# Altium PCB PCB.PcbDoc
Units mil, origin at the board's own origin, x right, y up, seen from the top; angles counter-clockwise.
Board outline 2745.03 x 2005.03 mil, 2 copper layers (Top Layer, Bottom Layer); 57 components, 30 nets, 243 pads, 20 vias.
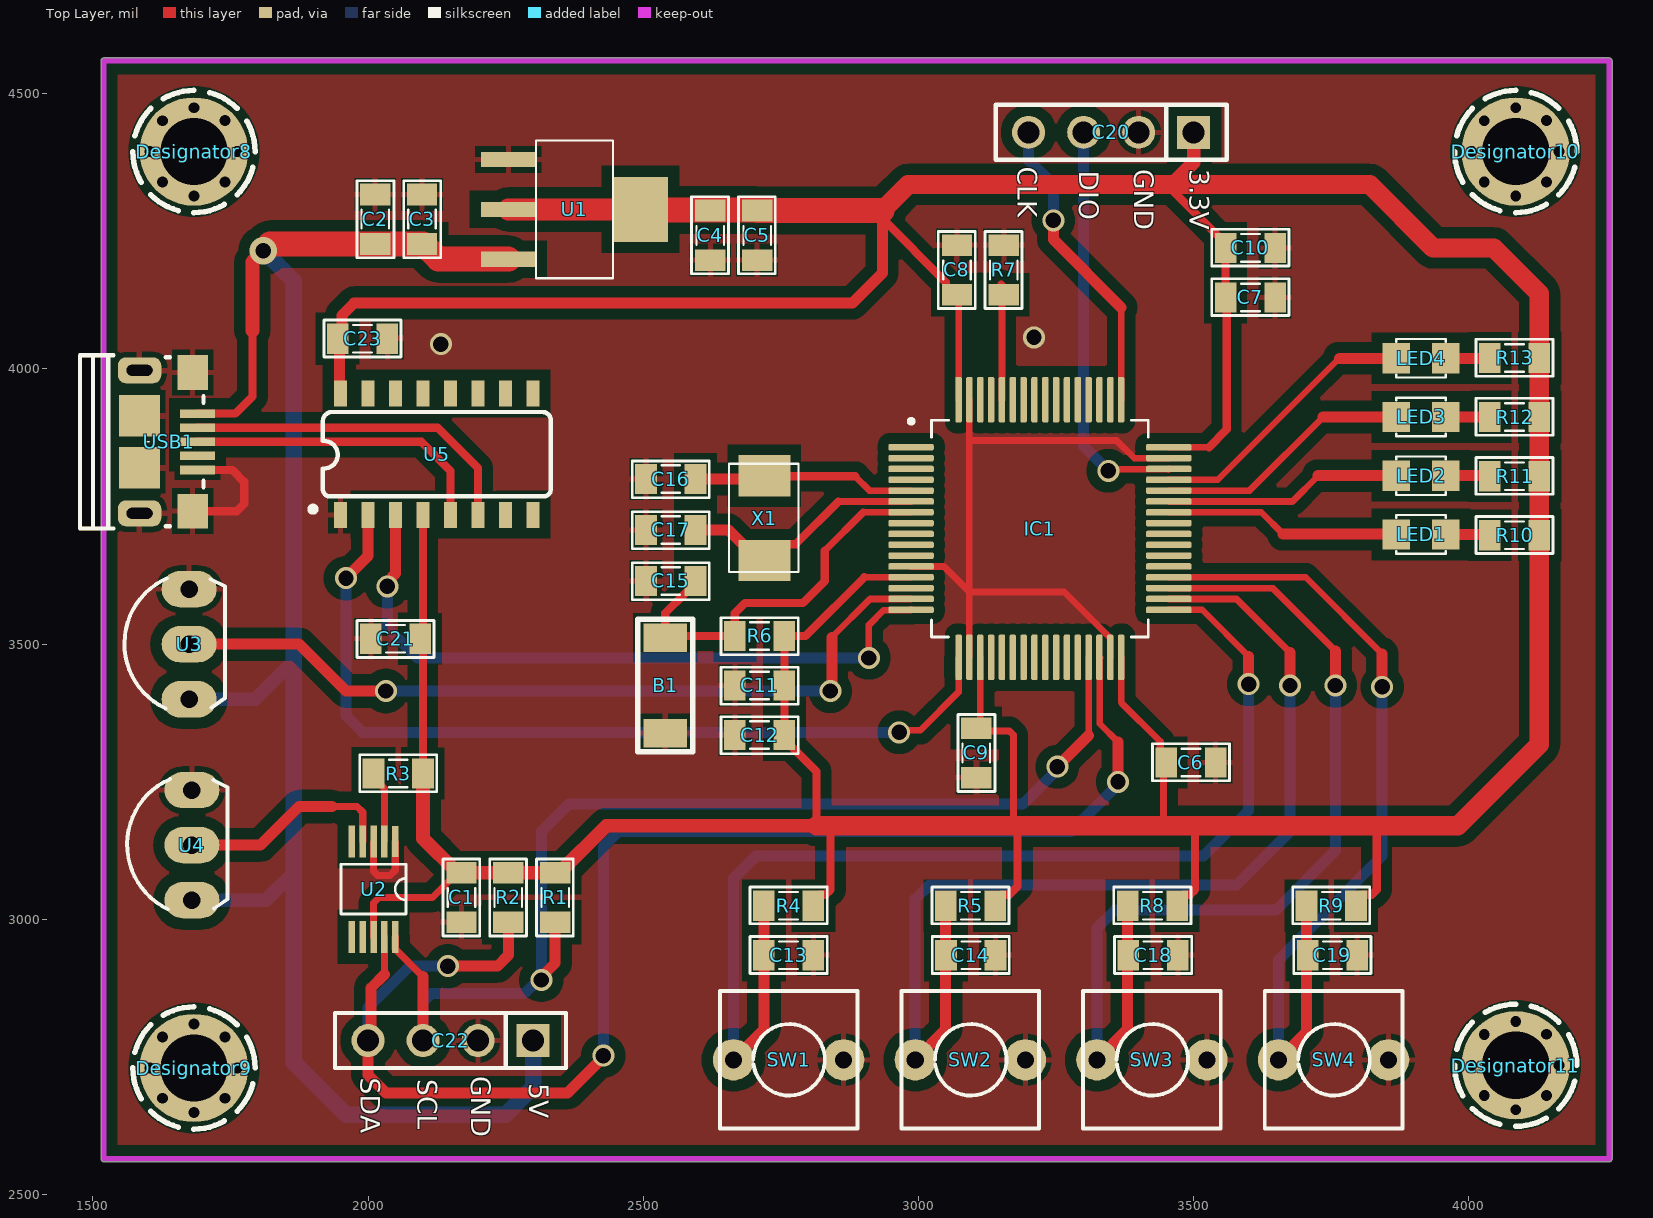
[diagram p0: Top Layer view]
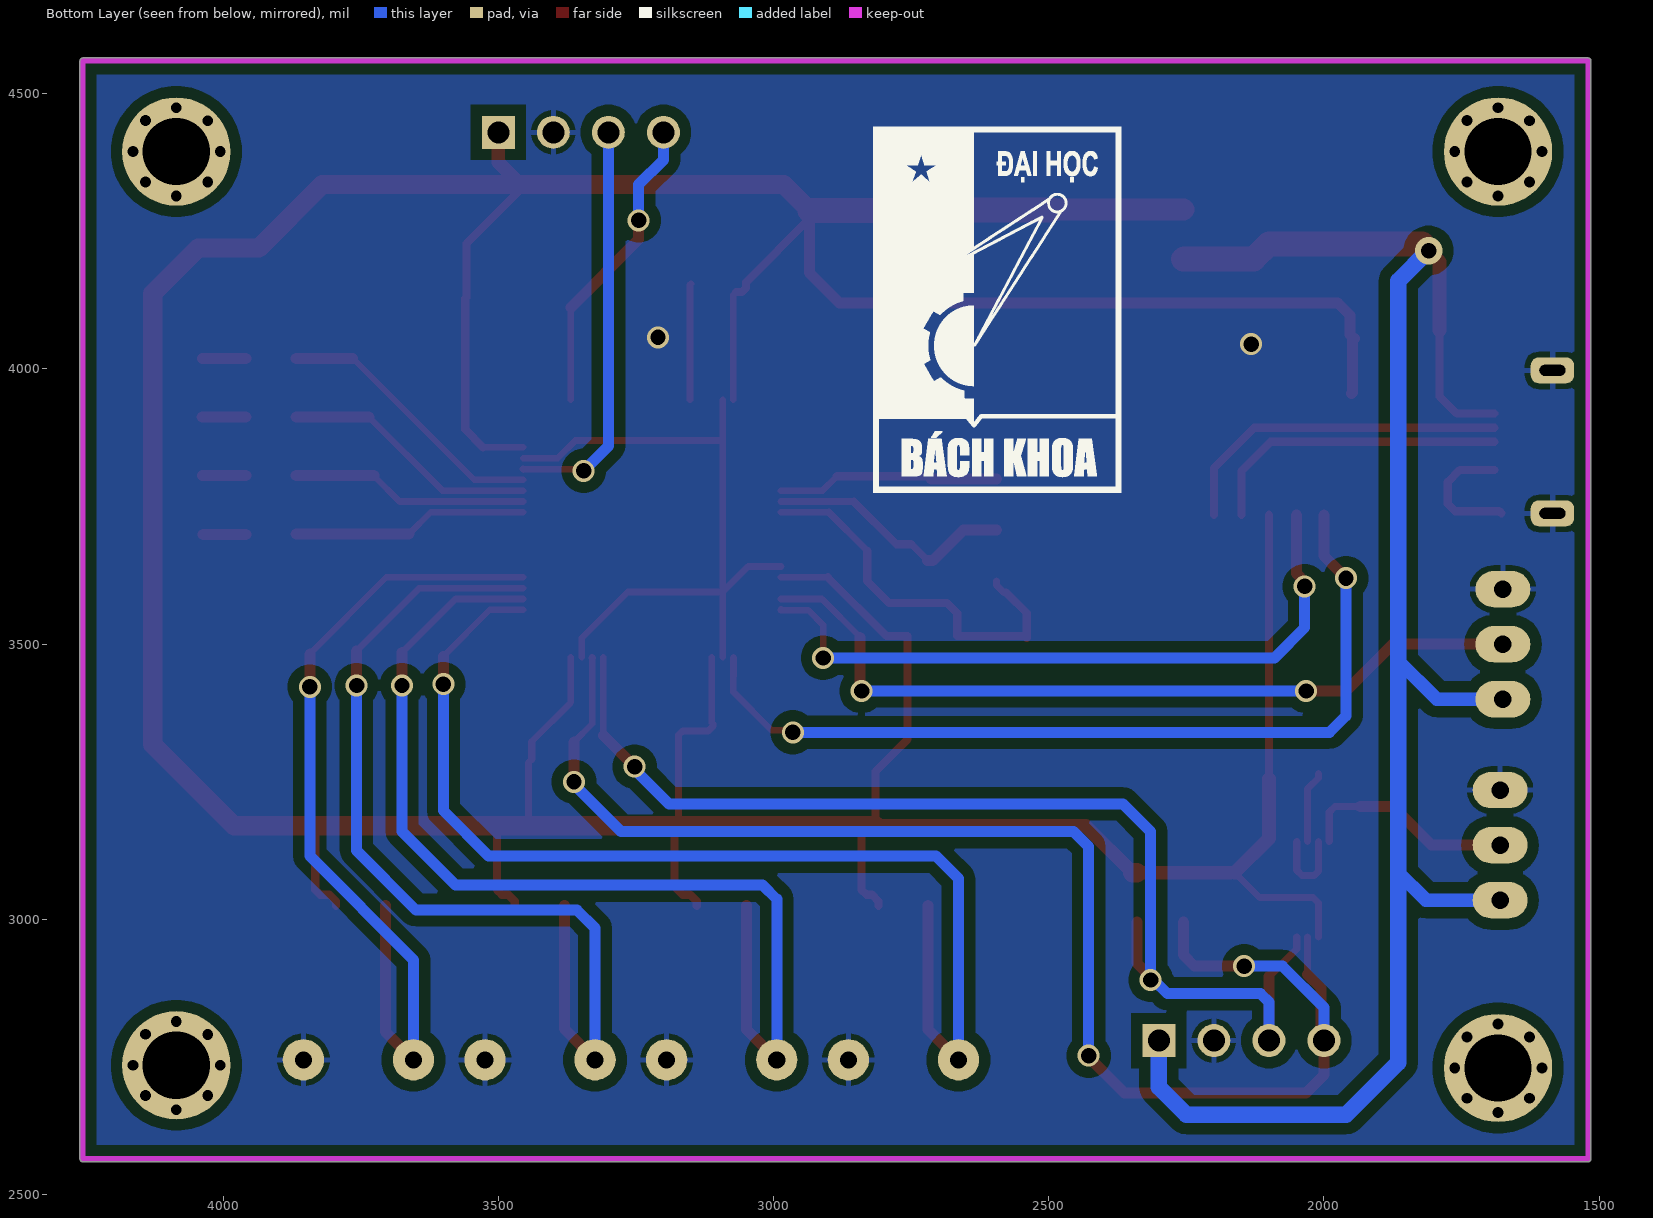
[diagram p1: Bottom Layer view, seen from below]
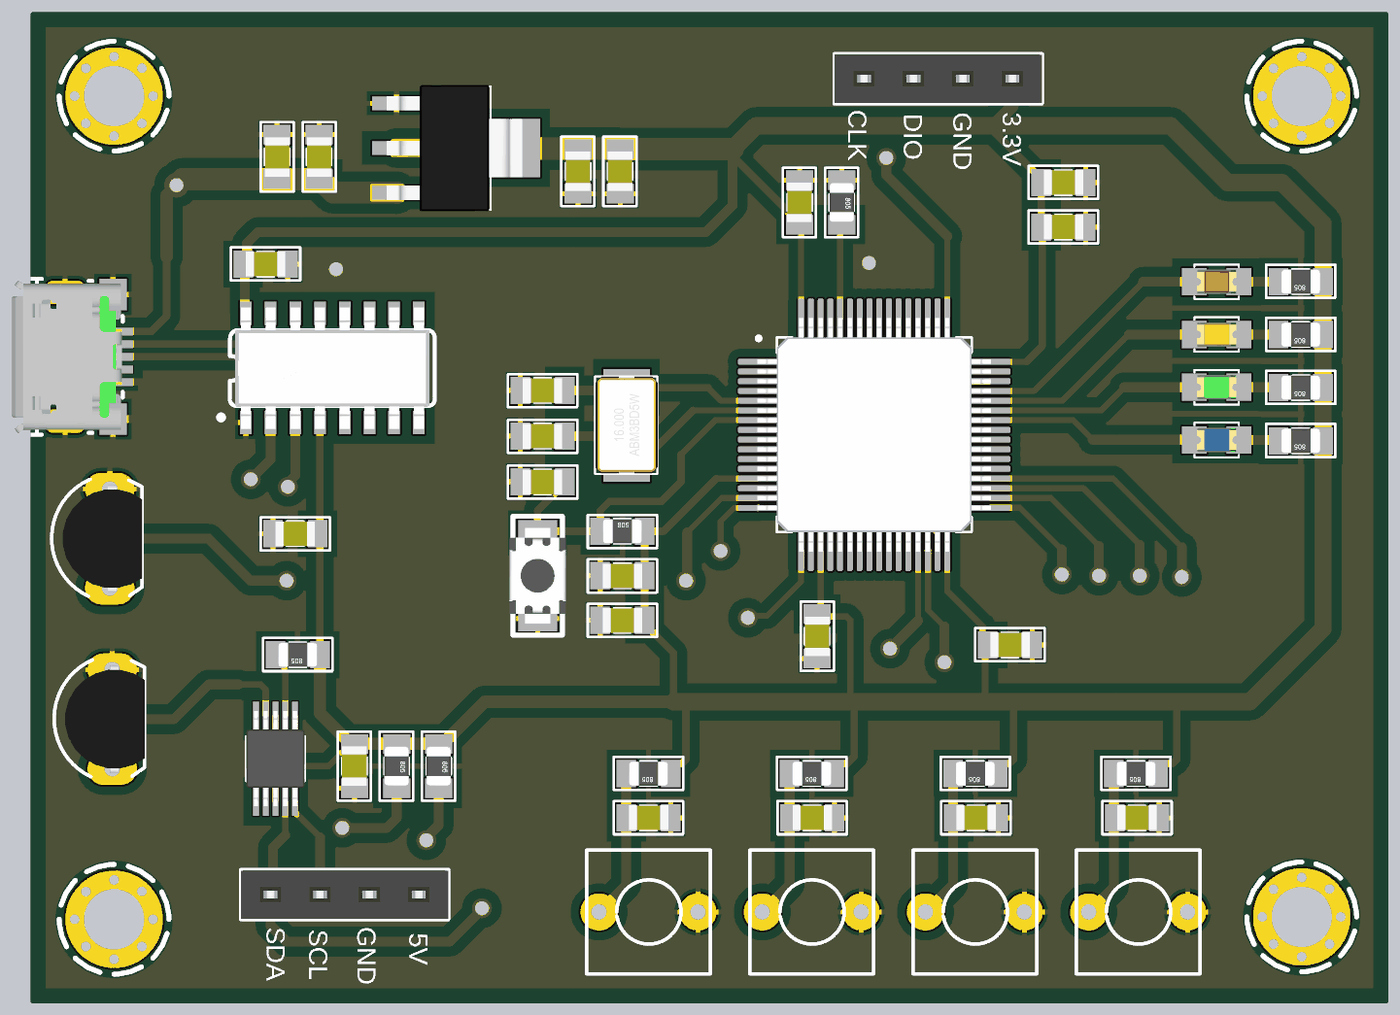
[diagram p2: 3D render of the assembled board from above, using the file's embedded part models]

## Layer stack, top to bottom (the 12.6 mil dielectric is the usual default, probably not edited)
Top Solder: solder mask 0.4, Solder Resist, Dk 3.5
Top Layer: signal copper 1.4
Dielectric 1: dielectric 12.6, FR-4, Dk 4.8
Bottom Layer: signal copper 1.4
Bottom Solder: solder mask 0.4, Solder Resist, Dk 3.5

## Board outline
1520,2559.99 cw(c1520,2565) 1514.98,2565 1514.98,4560 cw(c1520,4560) 1520,4565.02 4255,4565.02 cw(c4255,4560) 4260.02,4560 4260.02,2565 cw(c4255,2565) 4255,2559.99

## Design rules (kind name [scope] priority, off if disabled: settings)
Clearance Clearance_1 [InNet('GND')] p1: gap=20 ignorepadtopadclearanceinfootprint=TRUE
Clearance [All] p2: gap=15 ignorepadtopadclearanceinfootprint=TRUE
PolygonConnect [All] p1: thpad.connectstyle=Relief thpad.reliefconductorwidth=10 thpad.reliefentries=4 thpad.polygonreliefangle="90 Angle" thpad.airgapwidth=10 smdpad.connectstyle=Relief smdpad.reliefconductorwidth=10 smdpad.reliefentries=4 smdpad.polygonreliefangle="90 Angle" smdpad.airgapwidth=10 via.connectstyle=Direct via.reliefconductorwidth=10 via.reliefentries=4 via.polygonreliefangle="90 Angle" via.airgapwidth=10
RoutingVias [All] p1: holewidth=28 width=50 viastyle="Through Hole" minholewidth=28 minwidth=40 maxholewidth=28 maxwidth=50
SolderMaskExpansion [All] p1: expansion=4 istentingtop=FALSE
Width [All] p1: maxlimit=100 minlimit=10 preferedwidth=10
30 further rules are at their usual default settings.

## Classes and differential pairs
component class SCHE: B1 C1 C2 C3 C4 C5 C6 C7 C8 C9 C10 C11 C12 C13 C14 C15 C16 C17 C18 C19 C20 C21 C22 C23 IC1 LED1 LED2 LED3 LED4 R1 R2 R3 R4 R5 R6 R7 R8 R9 R10 R11 R12 R13 SW1 SW2 SW3 SW4 U1 U2 U3 U4 U5 USB1 X1

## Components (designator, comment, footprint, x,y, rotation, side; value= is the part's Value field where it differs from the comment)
B1 "Button 3x4x2.5" "Button 3x4x2.5" 2540,3425 r270 top
C1 "100nF" CAP_0805 2258.11,3042.15 r270 top value=33p
C2 "100nF" CAP_0805 1925,4270 r90 top value=33p
C3 "10uF" CAP_0805 2010,4270 r90 top value=33p
C4 "10uF" CAP_0805 2710,4245 r270 top value=33p
C5 "100nF" CAP_0805 2795,4245 r270 top value=33p
C6 "100nF" CAP_0805 3497.15,3196.89 r180 top value=33p
C7 "100nF" CAP_0805 3605.15,4041.89 r180 top value=33p
C8 "100nF" CAP_0805 3158.11,4182.15 r270 top value=33p
C9 "100nF" CAP_0805 3016.89,3300.35 r90 top value=33p
C10 "4.7uF" CAP_0805 3605.15,4131.89 r180 top value=33p
C11 "100nF" CAP_0805 2709.32,3513.11 r0 top value=33p
C12 "1uF" CAP_0805 2709.32,3423.11 r0 top value=33p
C13 "100nF" CAP_0805 2766.32,2846.89 r180 top value=33p
C14 "100nF" CAP_0805 3097.27,2846.89 r180 top value=33p
C15 "100nF" CAP_0805 2547.85,3703.11 r0 top value=33p
C16 "22pF" CAP_0805 2547.85,3888.11 r0 top value=33p
C17 "22pF" CAP_0805 2547.85,3795.61 r0 top value=33p
C18 "100nF" CAP_0805 3428.5,2846.89 r180 top value=33p
C19 "100nF" CAP_0805 3754.17,2846.89 r180 top value=33p
C20 "JP4" JP4-C1T 3500,4430 r180 top
C21 "100nF" CAP_0805 2047.85,3598.11 r0 top value=33p
C22 "JP4" JP4-C1T 2300,2780 r180 top
C23 "100nF" CAP_0805 1992.15,3966.89 r180 top value=33p
Designator8 "Comment" HOLD 1683.73,4395 r0 top
Designator9 "Comment" HOLD 1683.73,2730.12 r0 top
Designator10 "Comment" HOLD 4085,4395 r0 top
Designator11 "Comment" HOLD 4085,2735 r0 top
IC1 "STM32F103RCT6" STM32F103RCT6 3225,3720 r0 top
LED1 "LED" LED-0805-Blue 3958,3699.5 r180 top value="LED 3 ly Single Colour"
LED2 "LED" LED-0805-Green 3958,3806.17 r180 top value="LED 3 ly Single Colour"
LED3 "LED" LED-0805-Orange 3958,3912.83 r180 top value="LED 3 ly Single Colour"
LED4 "LED" LED-0805-Red 3958,4019.5 r180 top value="LED 3 ly Single Colour"
R1 "10k" RES-SMD-0805 2340,3040 r270 top
R2 "10k" RES-SMD-0805 2255,3040 r270 top
R3 "1k" RES-SMD-0805 2055,3265 r180 top
R4 "10k" RES-SMD-0805 2764.17,3025 r180 top
R5 "10k" RES-SMD-0805 3094.45,3025 r180 top
R6 "10k" RES-SMD-0805 2711.47,3515 r0 top
R7 "100k" RES-SMD-0805 3155,4180 r270 top
R8 "10k" RES-SMD-0805 3425,3025 r180 top
R9 "10k" RES-SMD-0805 3750,3025 r180 top
R10 "1k" RES-SMD-0805 4083,3698 r180 top
R11 "1k" RES-SMD-0805 4083,3805.33 r180 top
R12 "1k" RES-SMD-0805 4083,3912.67 r180 top
R13 "1k" RES-SMD-0805 4083,4020 r180 top
SW1 "SW" SW2 2864.17,2745 r180 top value="SW chip 2 pin"
SW2 "SW" SW2 3194.17,2745 r180 top value="SW chip 2 pin"
SW3 "SW" SW2 3524.17,2745 r180 top value="SW chip 2 pin"
SW4 "SW" SW2 3854.17,2745 r180 top value="SW chip 2 pin"
U1 "LM1117-ADJ" LM1117-SOP 2305,4290 r270 top
U2 "ADS1115IDGSR" VSOP-10_19.6_230_57X12_SMD 2010,3055 r270 top
U3 "LM35" QTO-92 1675,3500 r90 top
U4 "LM35" QTO-92 1680,3135 r90 top
U5 "CH340C" SO016 2125,3845.24 r0 top
USB1 "USB Micro 5p DIP" "USB Micro 5p DIP" 1585,3867.76 r270 top
X1 "8Mhz" "XTAL 5032 SMD" 2720,3730 r90 top value=4Mhz

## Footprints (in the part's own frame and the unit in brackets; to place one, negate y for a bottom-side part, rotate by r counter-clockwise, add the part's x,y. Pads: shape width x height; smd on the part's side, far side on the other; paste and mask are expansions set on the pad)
"Button 3x4x2.5" [mm]
  rect 1.3x2 smd: 1(-2.2,0) 2(2.2,0)
  silkscreen extent -3.05,-1.27 3.05,1.27, body extent -2.45,-1.45 2.45,1.45, height 2
CAP_0805 [mil]
  rect 39.37x55 smd: 1(-42.85,-88.11) 2(47.15,-88.11)
  silkscreen extent -68,-122 72,-55, body extent -38,-114 42,-64, height 24
HOLD [mm]
  round 0.5 hole 0.5: 2(-2.025,0) 2(-1.45,-1.4) 2(-1.45,1.425) 2(0,-2.05) 2(0,2.025) 2(1.429,-1.4) 2(1.429,1.434) 2(2,0)
  round 5 hole 3.1: 10(0,0)
  silkscreen extent -2.82,-2.82 2.82,2.82
JP4-C1T [mm] "4 row, straight, gold plating"
  rect 1.52x1.52 hole 1.02: 1(0,0)
  round 1.52 hole 1.02: 2(2.54,0) 3(5.08,0) 4(7.62,0)
  silkscreen extent -1.52,-1.27 9.14,1.27, body extent -1.52,-1.25 9.14,1.25, height 8.51
LED-0805-Blue [mil]
  rect 50x55 smd: 1(0,0) 2(90,0)
  silkscreen extent 0,-35 90,35, body extent 5,-25 85,25, height 43
LED-0805-Green [mil]
  rect 50x55 smd: 1(0,0) 2(90,0)
  silkscreen extent 0,-35 90,35, body extent 5,-25 85,25, height 43
LED-0805-Orange [mil]
  rect 50x55 smd: 1(0,0) 2(90,0)
  silkscreen extent 0,-35 90,35, body extent 5,-25 85,25, height 43
LED-0805-Red [mil]
  rect 50x55 smd: 1(0,0) 2(90,0)
  silkscreen extent 0,-35 90,35, body extent 5,-25 85,25, height 43
LM1117-SOP [mm]
  rect 0.7x2.54 smd: 1(-2.3,-1.27) 2(0,-1.27) 3(2.3,-1.27)
  rect 3x2.54 smd: 2(0,4.826)
  silkscreen extent -3.18,0 3.18,3.56, body extent -3.25,-1.78 3.25,5.18, height 1.68
QTO-92 [mil] "TO-92"
  oval 66x100 hole 32: 1(-100,0) 2(0,0) 3(100,0)
  silkscreen extent -117,-65 120,118, body extent -109,-66 109,95, height 245
RES-SMD-0805 [mil]
  rect 39.37x55 smd: 1(-45,0) 2(45,0)
  silkscreen extent -70,-34 70,33, body extent -39,-25 39,25, height 31
SO016 [mm]
  rect 0.6x1.2 smd: 1(-4.445,-2.8) 2(-3.175,-2.8) 3(-1.905,-2.8) 4(-0.635,-2.8) 5(0.635,-2.8) 6(1.905,-2.8) 7(3.175,-2.8) 8(4.445,-2.8) 9(4.445,2.8) 10(3.175,2.8) 11(1.905,2.8) 12(0.635,2.8) 13(-0.635,2.8) 14(-1.905,2.8) 15(-3.175,2.8) 16(-4.445,2.8)
  silkscreen extent -5.84,-2.67 5.26,1.95, body extent -4.99,-3.13 4.99,3.1, height 1.58
STM32F103RCT6 [mm]
  rrect50% 2.1x0.3 smd: 1(-6.057,3.499) 2(-6.057,2.999) 3(-6.057,2.499) 4(-6.057,1.999) 5(-6.057,1.499) 6(-6.057,0.999) 7(-6.057,0.499) 8(-6.057,-0.001) 9(-6.057,-0.501) 10(-6.057,-1.001) 11(-6.057,-1.501) 12(-6.057,-2.001) 13(-6.057,-2.501) 14(-6.057,-3.001) 15(-6.057,-3.501) 16(-6.057,-4.001) 33(5.833,-4.001) 34(5.833,-3.501) 35(5.833,-3.001) 36(5.833,-2.501) 37(5.833,-2.001) 38(5.833,-1.501) 39(5.833,-1.001) 40(5.833,-0.501) 41(5.833,-0.001) 42(5.833,0.499) 43(5.833,0.999) 44(5.833,1.499) 45(5.833,1.999) 46(5.833,2.499) 47(5.833,2.999) 48(5.833,3.499)
  rrect50% 0.3x2.1 smd: 17(-3.862,-6.196) 18(-3.362,-6.196) 19(-2.862,-6.196) 20(-2.362,-6.196) 21(-1.862,-6.196) 22(-1.362,-6.196) 23(-0.862,-6.196) 24(-0.362,-6.196) 25(0.138,-6.196) 26(0.638,-6.196) 27(1.138,-6.196) 28(1.638,-6.196) 29(2.138,-6.196) 30(2.638,-6.196) 31(3.138,-6.196) 32(3.638,-6.196) 49(3.638,5.694) 50(3.138,5.694) 51(2.638,5.694) 52(2.138,5.694) 53(1.638,5.694) 54(1.138,5.694) 55(0.638,5.694) 56(0.138,5.694) 57(-0.362,5.694) 58(-0.862,5.694) 59(-1.362,5.694) 60(-1.862,5.694) 61(-2.362,5.694) 62(-2.862,5.694) 63(-3.362,5.694) 64(-3.862,5.694)
  silkscreen extent -6.15,-5.25 4.89,4.8, body extent -6.11,-6.25 5.89,5.75, height 1.74
SW2 [mil] "SW button 2pin, 250x 250 mil"
  round 75 hole 31: 1(0,0) 2(200,0)
  silkscreen extent -25,-125 225,125
"USB Micro 5p DIP" [mm]
  rect 0.4x1.6 smd mask+0.05: 1(-1.3,2.675) 2(-0.65,2.675) 3(0,2.675) 4(0.65,2.675) 5(1.3,2.675)
  rrect60% 1.2x2 hole 0.5 slot 1.2 at 90 deg: 5(-3.3,0) 5(3.3,0)
  rect 1.6x1.4 smd: 5(-3.2,2.45) 5(3.2,2.45)
  rect 1.9x1.9 smd paste-10: 5(-1.2,0) 5(1.2,0)
  silkscreen extent -4,-2.75 4,2.95, body extent -3.93,-2.76 3.93,2.9, height 2.85
VSOP-10_19.6_230_57X12_SMD [mm] "VSOP Package"
  rect 1.45x0.3 smd mask+0.076: 1(-2.2,1)
  rect 1.47x0.3 smd mask+0.076: 2(-2.2,0.5) 3(-2.2,0) 4(-2.2,-0.5) 5(-2.2,-1) 6(2.2,-1) 7(2.2,-0.5) 8(2.2,0) 9(2.2,0.5) 10(2.2,1)
  silkscreen extent -1.15,-1.5 1.15,1.5, body extent -2.45,-1.5 2.45,1.5, height 1.07
"XTAL 5032 SMD" [mm] "SMD 5032 XTAL Footprint"
  rect 1.9x2.4 smd: 1(-1.981,0) 2(1.93,0)
  silkscreen extent -2.51,-1.57 2.49,1.63, body extent -2.5,-1.6 2.5,1.6, height 1.31

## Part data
C1 C2 C3 C4 C5 C6 C7 C8 C9 C10 C11 C12 C13 C14 C15 C16 C17 C18 C19 C21 C23: library part CapSMD, "Capacitor"
C20 C22: "WR-PHD 2.54 mm Angled Socket Header", Manufacturer="W¨¹rth Elektronik eiSos GmbH", partNo=613004143121
LED1 LED2 LED3 LED4: "LED Single colour Green and Red"
R1 R2 R3 R7: library part "Resistor - SMD", "Resistor", Manufacturer="Generic Components"
R4 R5 R6 R8 R9 R10 R11 R12 R13: library part "Resistor - SMD", "Resistor SMD", Manufacturer="Generic Components"
SW1 SW2 SW3 SW4: library part SW2, "Switch button 2 pin"
U1: "800mA Low-Dropout Linear Regulator"
U2: library part IC_ADS1115IDGSR, "Analog to Digital Converters - ADC 16B ADC w/ Int MUX PGA Comp Osc & Ref", Alternate Part Number-1=NA, Case/Package=MSOP-10, Manufacturer="Texas Instruments", Supplier Part Number-1=595-ADS1115IDGSR
U3 U4: "Teminal"
U5: "USB to serial chip CH340", Package=Package
USB1: "USB Type B"
X1: library part XT2, "Crystal For all Crystal 2pin."

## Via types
v1: diameter 40, hole 28, Top Layer to Bottom Layer, tented both sides, 19 vias
v2: diameter 50, hole 28, Top Layer to Bottom Layer, tented both sides, 1 vias

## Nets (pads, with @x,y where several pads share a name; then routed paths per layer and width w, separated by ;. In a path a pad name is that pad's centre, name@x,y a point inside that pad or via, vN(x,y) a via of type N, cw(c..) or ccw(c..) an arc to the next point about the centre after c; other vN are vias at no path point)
+3.3V: C1.1 C4.1 C5.1 C6.2 C7.2 C8.2 C9.2 C10.2 C11.2 C12.2 C20.1 C21.2 C23.2 IC1.13 IC1.19 IC1.32 IC1.48 IC1.64 R1.1 R2.1 R3.1 R4.1 R5.1 R6.2 R8.1 R9.1 R10.1 R11.1 R12.1 R13.1 U1.2 U2.8 U5.4 U5.16 | length 10158.1
  Top Layer w12: 2901.54,3621.54 IC1.13 ; IC1.64 C8.2@3072.95,4135 ; C9.2@3110,3355 3112.32,3357.32 IC1.19 ; IC1.32 3368.23,3394.27 3439.37,3323.13 ; IC1.48 3527.76,3857.76
  Top Layer w13: U2.8 2010,3030 2020,3040 2117.19,3040 2149,3071.81 2158.28,3081.09 C1.1@2166.09,3081.09 ; C1.1@2162.19,3085 C1.1 ; C9.2@3110,3355 3110,3351 3118.5,3342.5 3164.88,3342.5 3172.5,3334.88 3172.5,3170 ; 3439.37,3323.13 3439.37,3290.63 3445,3285 3445,3170
  Top Layer w15: R3.1@2100,3255 2100,3510 U5.4 ; R4.1 2809.17,3032.81 2821.36,3045 2831.21,3045 2840,3053.79 2840,3170 ; 2815,3170 2815,3268.65 2756.47,3327.19 C12.2 C11.2 R6.2 2795,3515 2901.54,3621.54 ; 2934.33,4273.17 3050,4157.5 3050,4147.19 3057.49,4139.7 C8.2@3067.8,4139.7 ; R5.1 3139.45,3032.81 3151.63,3045 3165,3045 3180,3060 3180,3170 ; 3460,4335 3460,4325.81 3558,4227.81 C10.2 C7.2 3560,4128 3560,3890 3527.76,3857.76 ; R8.1 3470,3032.82 3482.18,3045 3493.71,3045 3502.5,3053.79 3502.5,3170 ; R9.1 3795,3032.81 3807.19,3045 3823.71,3045 3832.5,3053.79 3832.5,3170
  Top Layer w20: U5.16 1948.19,3957.28 1948.19,4051.81 C23.2 1952.31,4062.31 1952.31,4097.31 1975,4120 2085,4120 2880,4120 2934.33,4174.33 2934.33,4273.17 2934.33,4287.85
  Top Layer w25: R3.1@2100,3255 2100,3147.18 C1.1@2162.19,3085 ; C1.1 R1.1 ; R1.1@2347.81,3085 2432.82,3170 2815,3170 ; 3460,4335 3500,4375 C20.1
  Top Layer w35: R1.1 R1.1@2347.81,3085 ; 2815,3170 2840,3170 3172.5,3170 3180,3170 3445,3170 3502.5,3170 3832.5,3170 3980,3170 4128,3318 R10.1 R11.1 R12.1 R13.1 4128,4137 4045,4220 3935,4220 3820,4335 3460,4335 2981.48,4335 2935.74,4289.26 2934.33,4287.85
  Top Layer w40: U1.2@2255,4290 U1.2@2495,4290
  Top Layer w45: U1.2@2495,4290 2496.07,4288.93 2621.89,4288.93 2705.82,4288.93 C5.1 2934.33,4287.85
+5: C2.1 C3.1 C22.1 U1.3 U3.1 U4.1 USB1.1 | length 3349.9
  Top Layer w15: USB1.1 1758.94,3918.94 1790,3950 1790,4070
  Top Layer w25: 1790,4070 1790,4195 v2(1810,4215)
  Top Layer w45: v2(1810,4215) 1822.15,4227.15 C2.1 C3.1 2100.3,4227.15 2127.44,4200 2254.45,4200 U1.3
  Bottom Layer w25: U3.1 1795,3400 1865,3470 ; U4.1 1815,3035 1865,3085
  Bottom Layer w30: v2(1810,4215) 1865,4160 1865,3470 1865,3085 1865,2740 1960,2645 2250,2645 2300,2695 C22.1
BUT0: C13.2 IC1.33 R4.2 SW1.2 | length 2079.7
  Top Layer w12: IC1.33 3515.48,3562.48 3600,3477.96
  Top Layer w20: SW1.2 2719.17,2800 R4.2 ; v1(3600,3427.5) 3600,3477.96
  Bottom Layer w20: SW1.2 2664.17,3074.17 2705,3115 3517.5,3115 3600,3197.5 v1(3600,3427.5)
BUT1: C14.2 IC1.34 R5.2 SW2.2 | length 1912.1
  Top Layer w12: IC1.34 3577.83,3582.17 3675,3485
  Top Layer w20: SW2.2 3049.45,2800.28 R5.2 ; v1(3675,3425) 3675,3485
  Bottom Layer w20: SW2.2 2994.17,3036.67 3020,3062.5 3577.5,3062.5 3675,3160 v1(3675,3425)
BUT2: C18.2 IC1.35 R8.2 SW3.2 | length 1746.7
  Top Layer w12: IC1.35 3643.15,3601.85 3757.5,3487.5
  Top Layer w20: SW3.2 3380,2800.83 R8.2 ; v1(3757.5,3425) 3757.5,3487.5
  Bottom Layer w20: SW3.2 3324.17,2984.17 3357.5,3017.5 3650,3017.5 3757.5,3125 v1(3757.5,3425)
BUT3: C19.2 IC1.36 R9.2 SW4.2 | length 1562
  Top Layer w12: IC1.36 3703.46,3621.54 3842.5,3482.5
  Top Layer w20: SW4.2 3705,2795.83 R9.2 ; v1(3842.5,3422.5) 3842.5,3482.5
  Bottom Layer w20: SW4.2 3654.17,2926.67 3842.5,3115 v1(3842.5,3422.5)
CH340_RXD: IC1.16 U5.3 | length 1256.9
  Top Layer w12: v1(2910,3475) 2910,3535 2936.89,3561.89 IC1.16@2985.94,3561.89
  Top Layer w13: IC1.16@2985.94,3561.89 IC1.16
  Top Layer w20: v1(2035,3605) 2035,3613.12 2050,3628.12 U5.3
  Bottom Layer w20: v1(2035,3605) 2035,3530 2090,3475 v1(2910,3475)
CH340_TXD: IC1.17 U5.2 | length 1600.3
  Top Layer w12: v1(2965,3340) 2968.62,3343.62 3003.62,3343.62 3072.95,3412.95 IC1.17@3072.95,3441.82
  Top Layer w13: IC1.17@3072.95,3441.82 IC1.17
  Top Layer w20: v1(1960,3620) 2000,3660 U5.2
  Bottom Layer w20: v1(1960,3620) 1960,3370 1990,3340 v1(2965,3340)
D_N: U5.6 USB1.2 | length 625.1
  Top Layer w15: USB1.2 2126.65,3893.35 2200,3820 U5.6
D_P: U5.5 USB1.3 | length 561.5
  Top Layer w15: USB1.3 2097.24,3867.76 2150,3815 U5.5
GND: B1.2 C1.2 C2.2 C3.2 C4.2 C5.2 C6.1 C7.1 C8.1 C9.1 C10.1 C11.1 C12.1 C13.1 C14.1 C15.1 C16.1 C17.1 C18.1 C19.1 C20.2 C21.1 C22.2 C23.1 IC1.12 IC1.18 IC1.31 IC1.47 IC1.63 R7.1 SW1.1 SW2.1 SW3.1 SW4.1 U1.1 U2.1 U2.3 U3.3 U4.3 U5.1 USB1.5 | length 1688.8
  Top Layer w12: v1@2130,4042.5 v1(2132.5,4045) ; IC1.12 3046.28,3641.22 3092.64,3594.86 ; IC1.18 3092.64,3594.86 ; IC1.63 3092.64,3870 ; IC1.31 3348.54,3511.31 3264.99,3594.86 3092.64,3594.86 ; IC1.47 3391.93,3838.07 3360,3870 3092.64,3870 ; 3092.64,3594.86 3092.64,3870
  Top Layer w13: U2.3 2010,3087.62 2017.62,3080 2040,3080 2049.37,3089.37 U2.1
  Top Layer w15: USB1.5@1677.52,3737.83 1681.46,3741.77 1761.77,3741.77 1775,3755 1775,3795 1753.43,3816.57 USB1.5@1690.32,3816.57
  other v1: 3210,4057.5
LED0: IC1.42 LED1.2 | length 430
  Top Layer w12: IC1.42 3622.85,3739.65 3662.5,3700
  Top Layer w13: LED1.2@3867.5,3700 LED1.2
  Top Layer w20: 3662.5,3700 LED1.2@3867.5,3700
LED1: IC1.43 LED2.2 | length 432.8
  Top Layer w12: IC1.43 3679.33,3759.33 3726.17,3806.17
  Top Layer w20: 3726.17,3806.17 LED2.2
LED2: IC1.44 LED3.2 | length 468.8
  Top Layer w12: IC1.44 3601.52,3779.02 3735.33,3912.83
  Top Layer w20: 3735.33,3912.83 LED3.2
LED3: IC1.45 LED4.2 | length 504.8
  Top Layer w12: IC1.45 3543.7,3798.7 3764.5,4019.5
  Top Layer w20: 3764.5,4019.5 LED4.2
LM35_ADC1: IC1.15 U3.2 | length 1471.6
  Top Layer w12: 2842.5,3512.5 2912.17,3582.17 IC1.15
  Top Layer w20: U3.2 1875,3500 1960,3415 v1(2032.5,3415) ; v1(2840,3415) 2842.5,3417.5 2842.5,3512.5
  Bottom Layer w20: v1(2032.5,3415) v1(2840,3415)
LM35_ADC2: U2.4 U4.2 | length 396.7
  Top Layer w13: 1935,3205 1980,3205 1990.32,3194.68 U2.4
  Top Layer w20: U4.2 1805,3135 1875,3205 1935,3205
NetB1_1: B1.1 C15.2 IC1.7 R6.1 | length 726.3
  Top Layer w12: 2899.65,3739.65 IC1.7
  Top Layer w13: B1.1 B1.1@2543.39,3515 ; C15.2@2577.3,3594 2581.81,3594 2595,3607.19 C15.2 ; 2830,3670 2899.65,3739.65
  Top Layer w15: B1.1 2540,3556.7 C15.2@2577.3,3594 ; B1.1@2543.39,3515 R6.1 2666.47,3556.47 2685,3575 2790,3575 2830,3615 2830,3670
NetC16_2: C16.2 IC1.5 X1.2 | length 404.4
  Top Layer w12: 2885,3805 2910.98,3779.02 IC1.5
  Top Layer w13: X1.2@2714,3800 X1.2@2719,3805
  Top Layer w15: X1.2@2719,3805 2885,3805
  Top Layer w20: C16.2 X1.2@2714,3800
NetC17_2: C17.2 IC1.6 X1.1 | length 459
  Top Layer w12: 2854.33,3759.33 IC1.6
  Top Layer w13: X1.1 X1.1@2749.61,3681.61
  Top Layer w15: X1.1@2749.61,3681.61 2776.61,3681.61 2854.33,3759.33
  Top Layer w20: C17.2 2654.66,3707.5 2710.16,3652 X1.1
NetIC1_60: IC1.60 R7.2 | length 216.5
  Top Layer w12: 3150,4155 3151.69,4153.31 R7.2@3151.69,4135 ; IC1.60 R7.2@3151.69,4140
NetLED1_1: LED1.1 R10.2 | length 80.6
  Top Layer w13: R10.2@4036.5,3699.5 R10.2
  Top Layer w20: LED1.1 R10.2@4036.5,3699.5
NetLED2_1: LED2.1 R11.2 | length 80.3
  Top Layer w13: R11.2@4037.17,3806.17 R11.2
  Top Layer w20: LED2.1 R11.2@4037.17,3806.17
NetLED3_1: LED3.1 R12.2 | length 80.1
  Top Layer w13: LED3.1 LED3.1@3958.17,3912.67
  Top Layer w20: LED3.1@3958.17,3912.67 R12.2
NetLED4_1: LED4.1 R13.2 | length 80.2
  Top Layer w13: R13.2@4037.5,4019.5 R13.2
  Top Layer w20: LED4.1 R13.2@4037.5,4019.5
NetR3_2: R3.2 U2.2 | length 131.5
  Top Layer w13: R3.2 2010,3257.19 2029.68,3237.5 U2.2
SCL: C22.3 IC1.29 R1.2 U2.10 | length 2107.4
  Top Layer w12: 3309.17,3334.17 IC1.29
  Top Layer w13: U2.10 2049.37,2946.54 2100,2895.91
  Top Layer w20: C22.3 2100,2895.91 ; v1(2315,2890) 2315,2895.41 2340,2920.41 R1.2 ; v1(3252.5,3277.5) 3309.17,3334.17
  Bottom Layer w20: C22.3 2100,2850 2115,2865 2284.59,2865 2309.59,2890 v1(2315,2890) 2315,3160 2365,3210 3190,3210 3252.5,3272.5 v1(3252.5,3277.5)
SDA: C22.4 IC1.30 R2.2 U2.9 | length 2754.5
  Top Layer w12: IC1.30@3329.43,3475.49 3329.43,3355.57 3362.5,3322.5
  Top Layer w13: C22.4 C22.4@2005,2785 ; 2029.68,2899.68 U2.9 ; IC1.30 IC1.30@3329.43,3475.49
  Top Layer w20: C22.4 2000,2717.5 2032.5,2685 2362.5,2685 2427.5,2750 v1(2427.5,2752.5) ; C22.4@2005,2785 2005,2875 2029.68,2899.68 ; v1(2145,2915) 2235,2915 2255,2935 R2.2 ; v1(3362.5,3250) 3362.5,3322.5
  Bottom Layer w20: C22.4 2000,2840 2075,2915 v1(2145,2915) ; v1(2427.5,2752.5) 2427.5,3132.5 2455,3160 3277.5,3160 3362.5,3245 v1(3362.5,3250)
SWCLK: C20.4 IC1.49 | length 555.5
  Top Layer w12: IC1.49 3368.23,4111.77
  Top Layer w20: v1(3245,4270) 3245,4235 3368.23,4111.77
  Bottom Layer w20: C20.4 3200,4380 3245,4335 v1(3245,4270)
SWDIO: C20.3 IC1.46 | length 750.9
  Top Layer w12: v1(3345,3815) 3347.94,3817.94 IC1.46@3454.2,3817.94
  Top Layer w13: IC1.46@3454.2,3817.94 IC1.46
  Bottom Layer w13: C20.3 C20.3@3307.5,4422.5
  Bottom Layer w20: C20.3@3307.5,4422.5 3300,4415 3300,3860 v1(3345,3815)
pads on no net: Designator8.2 Designator8.10 Designator9.2 Designator9.10 Designator10.2 Designator10.10 Designator11.2 Designator11.10 IC1.1 IC1.2 IC1.3 IC1.4 IC1.8 IC1.9 IC1.10 IC1.11 IC1.14 IC1.20 IC1.21 IC1.22 IC1.23 IC1.24 IC1.25 IC1.26 IC1.27 IC1.28 IC1.37 IC1.38 IC1.39 IC1.40 IC1.41 IC1.50 IC1.51 IC1.52 IC1.53 IC1.54 IC1.55 IC1.56 IC1.57 IC1.58 IC1.59 IC1.61 IC1.62 U2.5 U2.6 U2.7 U5.7 U5.8 U5.9 U5.10 U5.11 U5.12 U5.13 U5.14 U5.15 USB1.4

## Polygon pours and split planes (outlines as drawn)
GND on Top Layer "100" (solid, pour order 0): 1520,4560 4255,4560 4255,2565 1520,2565
GND on Bottom Layer "100" (solid, pour order 1): 1520,4560 4255,4560 4255,2565 1520,2565

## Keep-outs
Keep-Out Layer:
  lines w10: 1520,2565 1520,4342.5 1520,4560 4255,4560 4255,2565 1520,2565

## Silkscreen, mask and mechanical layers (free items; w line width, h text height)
Top Overlay:
  text "CLK" at 3168.17,4367.5 h60 r270
  text "GND" at 3380.67,4362.5 h60 r270
  text "3.3V" at 3480.67,4362.5 h60 r270
  text "DIO" at 3280.67,4360 h60 r270
  text "GND" at 2175.67,2715 h60 r270
  text "SDA" at 1975,2712.5 h60 r270
  text "SCL" at 2078.17,2710 h60 r270
  text "5V" at 2280.67,2702.5 h60 r270
Bottom Overlay:
  drawing of 11642 lines, arcs and shapes, not listed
